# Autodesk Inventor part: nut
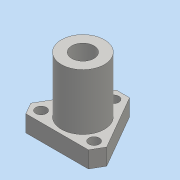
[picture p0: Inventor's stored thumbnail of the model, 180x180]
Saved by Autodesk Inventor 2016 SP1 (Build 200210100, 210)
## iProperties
Created: 2016-06
Part Number: nut
Material: Generic
Document SubType Name: Modeling
Designer: Mohamed A.
Density: 1 g/cm^3
Appearance: Default
Author: Mohamed A.
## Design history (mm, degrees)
sketch "Sketch1"
  geometry: L1 (-2.5, 14.957)-(2.5, 14.957); L2 (2.5, 14.957)-(14.203, -5.313); L3 (14.203, -5.313)-(11.703, -9.643); L4 (11.703, -9.643)-(-11.703, -9.643); L5 (-11.703, -9.643)-(-14.203, -5.313); L6 (-14.203, -5.313)-(-2.5, 14.957); L7 (0, 0)-(8.351, 4.822); L8 (0, 0)-(-8.351, 4.822); L9 (0, 0)-(0, -9.643); L10 (0, 0)-(12.953, -7.478); C1 r 4.15 at (0, 0); C2 r 2 at (9.922, -5.728); C3 r 2 at (0, 11.457); C4 r 2 at (-9.922, -5.728); 1 further point
  constraints: 20 end point, 6 equal length, 4 centre point, 4 midpoint, 3 parallel, 3 perpendicular, 1 coincident, 1 horizontal, 1 point on line, 7 other
  dimensions: "d0" = 24.6 distance between parallel lines of L4 L1; "d1" = 5 distance of L1.start L1.end; "d2" = 8.3 diameter of C1; "d4" = 4 diameter of C2; "d5" = 3.5 distance from line of L3 C2.centre; "d8" = 360 deg dimension on point (0, 0) C2.centre (derived)
extrude "Extrusion1" new body sketch "Sketch1" distance "d10" = 6.2; taper "d11" = 0 deg
sketch "Sketch2"
  geometry: C1 r 4.15 at (0, 0) reference; C2 r 8.05 at (0, 0); 1 further point
  constraints: 1 centre point, 1 coincident
  dimensions: "d12" = 16.1 diameter of C2
extrude "Extrusion2" join sketch "Sketch2" distance "d13" = 21; taper "d14" = 0 deg
body "Solid1"
